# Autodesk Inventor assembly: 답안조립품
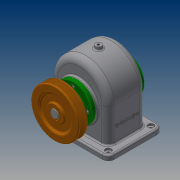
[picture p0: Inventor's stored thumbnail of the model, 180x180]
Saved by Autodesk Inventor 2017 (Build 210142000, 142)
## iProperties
Part Number: 답안조립품
Material: 일반
Document SubType Name: Assembly
Designer: 20
Author: 20
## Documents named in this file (13)
- C:\Users\20\Desktop\480310V1009\답안조립품.iam
- C:\Users\20\Desktop\480310V1009\본체.ipt
- C:\Users\20\Desktop\480310V1009\뒤커버.ipt
- C:\Users\20\Desktop\480310V1009\앞커버.ipt
- C:\Users\20\Desktop\480310V1009\베어링 6203.ipt
- C:\Users\20\Desktop\480310V1009\축.ipt
- C:\Users\20\Desktop\480310V1009\스퍼기어.ipt
- C:\Users\20\Desktop\480310V1009\키 6x6x22.ipt
- C:\Users\20\Desktop\480310V1009\오일 실 28 40 8.ipt
- C:\Users\20\Desktop\480310V1009\V-벨트풀리.ipt
- C:\Users\20\Desktop\480310V1009\키 5x5x18.ipt
- C:\Users\20\Desktop\480310V1009\멈춤나사 M4.ipt
- C:\Users\20\Desktop\480310V1009\볼트 M4.ipt
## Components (1 placed, 1 different names)
1. V-벨트풀리:1 — 플러쉬:2
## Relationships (1: Flush 1)
- 플러쉬:2 [Flush]: V-벨트풀리:1
